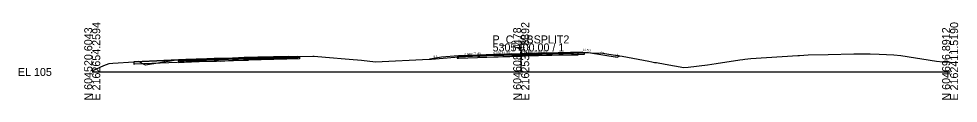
# Model space of a CAD drawing. Extents: x -26 to 1303, y -10 to 12033.
# Drawn here: x 974.3 to 1302.8, y 490.3 to 517.4 of the extents above; entities that cross this region are included whole.
import ezdxf

# ---------------------------------------------------------------- set-up
doc = ezdxf.new("R2010")
doc.units = 0
for name, color, linetype in [('RD_GPK_XS_Cell', 7, 'Continuous'), ('RD_XS_Base', 7, 'Continuous'), ('RD_XS_ExGround', 7, 'Continuous'), ('RD_XS_ExPaveRet', 7, 'Continuous'), ('RD_XS_Greenside', 7, 'Continuous'), ('RD_XS_Pave', 7, 'Continuous'), ('RD_XS_PaveOvlay_CP', 7, 'Continuous'), ('RD_XS_TieSlope', 7, 'Continuous'), ('RD_XS_TX_Elev_EX', 7, 'Continuous'), ('RD_XS_TX_Elev_PR', 7, 'Continuous'), ('RD_XS_TX_ShdSlope', 7, 'Continuous'), ('RD_XS_TX_Slope', 7, 'Continuous')]:
    doc.layers.add(name, color=color, linetype=linetype)

msp = doc.modelspace()

# ---------------------------------------------------------------- linework, layer by layer
at = {"layer": 'RD_GPK_XS_Cell'}
for p, q in [((1150, 500), (1150, 510)), ((1000, 500), (1150, 500)), ((1150, 500), (1300, 500))]:
    msp.add_line(p, q, dxfattribs=at)
at = {"layer": 'RD_XS_Base'}
for p, q in [((1150, 506.05), (1138, 505.72)), ((1150, 506.05), (1171.54, 506.66)), ((1150, 505.55), (1150, 506.21)), ((1150, 506.21), (1150, 506.21)), ((1150, 506.21), (1150, 506.21)), ((1150, 506.21), (1150, 506.05)), ((1172.04, 506.17), (1150, 505.55)), ((1150, 506.05), (1150, 506.05)), ((1150, 505.55), (1150, 506.05)), ((1150, 506.05), (1150, 506.05)), ((1150, 506.05), (1150, 506.05)), ((1162, 506.39), (1162, 506.39)), ((1162, 506.39), (1162, 506.39)), ((1171.54, 506.66), (1171.54, 506.66)), ((1172.04, 506.67), (1172.04, 506.17)), ((1172.04, 506.64), (1172.04, 506.64)), ((1030.19, 503.86), (1030.13, 503.86)), ((1030.13, 503.86), (1030.13, 503.42)), ((1030.13, 503.42), (1030.13, 503.36)), ((1030.13, 503.36), (1030.19, 503.36)), ((1030.63, 503.88), (1030.19, 503.86)), ((1030.19, 503.36), (1030.63, 503.38)), ((1032.1, 503.94), (1030.63, 503.88)), ((1030.63, 503.38), (1032.1, 503.44)), ((1042.63, 504.36), (1032.1, 503.94)), ((1032.1, 503.44), (1042.63, 503.86)), ((1044.14, 504.4), (1042.63, 504.36)), ((1042.63, 503.86), (1044.14, 503.9)), ((1054.63, 504.67), (1044.14, 504.4)), ((1044.14, 503.9), (1054.63, 504.17)), ((1054.63, 504.67), (1072.44, 505.13)), ((1054.63, 504.17), (1054.63, 504.83)), ((1054.63, 504.83), (1054.63, 504.83)), ((1054.63, 504.83), (1054.63, 504.83)), ((1054.63, 504.83), (1054.63, 504.67)), ((1054.63, 504.67), (1054.63, 504.67)), ((1054.63, 504.17), (1054.63, 504.67)), ((1054.63, 504.67), (1054.63, 504.67)), ((1054.63, 504.67), (1054.63, 504.67)), ((1072.44, 504.63), (1054.63, 504.17)), ((1054.63, 504.17), (1054.63, 504.17)), ((1071.94, 505.12), (1071.94, 505.12)), ((1072.44, 505.13), (1072.44, 504.63)), ((1072.44, 505.1), (1072.44, 505.1)), ((1128.08, 505.32), (1127.58, 505.3)), ((1127.58, 505.3), (1127.58, 505.3)), ((1127.58, 505.3), (1127.58, 504.8)), ((1127.58, 504.8), (1128.08, 504.82)), ((1138, 505.72), (1128.08, 505.32)), ((1128.08, 505.32), (1128.08, 505.32)), ((1128.08, 504.82), (1138, 505.22)), ((1128.08, 504.82), (1128.08, 504.82)), ((1138, 505.72), (1138, 505.72)), ((1138, 505.22), (1150, 505.55)), ((1138, 505.22), (1138, 505.22)), ((1150, 505.55), (1150, 505.55)), ((1162, 505.89), (1162, 505.89)), ((1162, 505.89), (1162, 505.89))]:
    msp.add_line(p, q, dxfattribs=at)
at = {"layer": 'RD_XS_ExGround'}
msp.add_lwpolyline([(1000, 500.38), (1004.09, 502.24), (1005.95, 502.99), (1007.16, 503.04), (1014.5, 503.53), (1033.44, 504.37), (1036.42, 504.49), (1042.96, 504.55), (1044.68, 504.73), (1045.03, 504.59), (1049.17, 504.86), (1053.17, 505.06), (1057.99, 505.21), (1063.44, 505.35), (1068.59, 505.43), (1077.12, 505.52), (1077.63, 505.53), (1081.56, 505.2), (1089.83, 504.5), (1094.2, 504.08), (1099.09, 503.58), (1117.86, 504.48), (1118.23, 504.5), (1118.6, 504.53), (1135, 505.89), (1140.45, 506.08), (1149.92, 506.38), (1150.27, 506.38), (1151.05, 506.43), (1152.22, 506.46), (1156.04, 506.54), (1160.68, 506.64), (1168.98, 506.76), (1169.88, 506.77), (1170.49, 506.76), (1178.54, 506.55), (1180.71, 506.2), (1185.37, 505.5), (1194.6, 503.76), (1195.68, 503.56), (1196.66, 503.37), (1197.27, 503.26), (1200.32, 502.72), (1206.91, 501.55), (1208.45, 501.72), (1215.14, 502.48), (1218.24, 502.99), (1226.49, 504.24), (1227.52, 504.41), (1228.18, 504.5), (1230.27, 504.66), (1246.74, 505.8), (1247.32, 505.81), (1250.35, 505.95), (1257.31, 506.11), (1266.34, 506.33), (1270.07, 506.36), (1272, 506.39), (1275.17, 506.18), (1280.29, 506.03), (1282.83, 505.75), (1295.24, 503.81), (1297.49, 503.56), (1299.13, 503.54), (1300, 503.44)], dxfattribs=at)
at = {"layer": 'RD_XS_ExPaveRet'}
for points in [[(1169.88, 506.77), (1168.98, 506.76), (1168.98, 506.76), (1160.68, 506.64), (1160.68, 506.64), (1160.68, 506.64), (1156.04, 506.54), (1156.04, 506.54), (1156.04, 506.54), (1152.22, 506.46), (1151.05, 506.43), (1151.05, 506.43), (1150.27, 506.38), (1150.27, 506.38), (1149.92, 506.38), (1149.92, 506.38), (1149.92, 506.38), (1140.45, 506.08), (1140.45, 506.08), (1135, 505.89), (1135, 505.89), (1135, 505.14), (1140.45, 505.33), (1140.45, 505.33), (1149.92, 505.63), (1149.92, 505.63), (1149.92, 505.63), (1150.27, 505.63), (1150.27, 505.63), (1151.05, 505.68), (1151.05, 505.68), (1152.22, 505.71), (1156.04, 505.79), (1156.04, 505.79), (1156.04, 505.79), (1160.68, 505.89), (1160.68, 505.89), (1160.68, 505.89), (1168.98, 506.01), (1168.98, 506.01), (1169.88, 506.02), (1169.88, 506.02), (1169.88, 506.77), (1169.88, 506.77), (1169.88, 506.77)], [(1169.88, 506.77), (1168.98, 506.76), (1160.68, 506.64), (1156.04, 506.54), (1152.22, 506.46), (1151.05, 506.43), (1150.27, 506.38), (1149.92, 506.38), (1140.45, 506.08), (1135, 505.89), (1135, 505.14), (1140.45, 505.33), (1149.92, 505.63), (1150.27, 505.63), (1151.05, 505.68), (1152.22, 505.71), (1156.04, 505.79), (1160.68, 505.89), (1168.98, 506.01), (1169.88, 506.02), (1169.88, 506.02), (1169.88, 506.77), (1169.88, 506.77)], [(1063.44, 505.35), (1058.03, 505.21), (1057.99, 505.21), (1057.87, 505.21), (1053.17, 505.06), (1053.11, 505.06), (1049.17, 504.86), (1049.1, 504.86), (1049.09, 504.86), (1045.02, 504.59), (1044.92, 504.59), (1044.68, 504.69), (1043.49, 504.56), (1043.38, 504.56), (1036.55, 504.49), (1036.45, 504.49), (1036.43, 504.48), (1036.39, 504.48), (1033.24, 504.36), (1032.78, 504.34), (1014.84, 503.55), (1014.5, 503.53), (1014.5, 503.53), (1014.5, 503.53), (1014.5, 503.5), (1014.5, 502.78), (1014.5, 502.78), (1014.5, 502.78), (1014.84, 502.8), (1032.78, 503.59), (1033.24, 503.61), (1036.39, 503.73), (1036.43, 503.73), (1036.45, 503.74), (1036.55, 503.74), (1043.38, 503.81), (1043.49, 503.81), (1044.68, 503.94), (1044.92, 503.84), (1045.02, 503.84), (1049.09, 504.11), (1049.1, 504.11), (1049.17, 504.11), (1053.11, 504.3), (1053.17, 504.31), (1057.87, 504.46), (1057.99, 504.46), (1058.03, 504.46), (1063.44, 504.6), (1063.56, 504.6), (1068.59, 504.68), (1068.59, 505.42), (1068.59, 505.43), (1063.56, 505.35), (1063.44, 505.35)], [(1063.44, 505.35), (1058.03, 505.21), (1057.99, 505.21), (1057.87, 505.21), (1053.17, 505.06), (1053.11, 505.06), (1049.17, 504.86), (1049.1, 504.86), (1049.09, 504.86), (1045.02, 504.59), (1044.92, 504.59), (1044.68, 504.69), (1043.49, 504.56), (1043.38, 504.56), (1036.55, 504.49), (1036.45, 504.49), (1036.43, 504.48), (1036.39, 504.48), (1033.24, 504.36), (1032.78, 504.34), (1014.84, 503.55), (1014.5, 503.53), (1014.5, 503.53), (1014.5, 503.5), (1014.5, 502.78), (1014.5, 502.78), (1014.84, 502.8), (1032.78, 503.59), (1033.24, 503.61), (1036.39, 503.73), (1036.43, 503.73), (1036.45, 503.74), (1036.55, 503.74), (1043.38, 503.81), (1043.49, 503.81), (1044.68, 503.94), (1044.92, 503.84), (1045.02, 503.84), (1049.09, 504.11), (1049.1, 504.11), (1049.17, 504.11), (1053.11, 504.3), (1053.17, 504.31), (1057.87, 504.46), (1057.99, 504.46), (1058.03, 504.46), (1063.44, 504.6), (1063.56, 504.6), (1068.59, 504.68), (1068.59, 505.42), (1068.59, 505.43), (1063.56, 505.35), (1063.44, 505.35)]]:
    msp.add_lwpolyline(points, dxfattribs=at)
at = {"layer": 'RD_XS_Greenside'}
for p, q in [((1173.54, 506.81), (1183.54, 505.15)), ((1018.63, 502.37), (1016.16, 503.61)), ((1028.63, 504.04), (1018.63, 502.37)), ((1122.08, 505.16), (1118.07, 504.49)), ((1183.54, 505.15), (1184.5, 505.63))]:
    msp.add_line(p, q, dxfattribs=at)
at = {"layer": 'RD_XS_Pave'}
for p, q in [((1138, 506.04), (1128.08, 505.64)), ((1150, 506.37), (1138, 506.04)), ((1138, 505.88), (1150, 506.21)), ((1150, 506.21), (1138, 505.88)), ((1138, 505.72), (1150, 506.05)), ((1138, 506.04), (1138, 506.04)), ((1171.54, 506.97), (1150, 506.37)), ((1171.54, 506.82), (1150, 506.21)), ((1150, 506.21), (1171.54, 506.82)), ((1150, 506.05), (1172.04, 506.67)), ((1150, 506.37), (1150, 506.37)), ((1150, 506.21), (1150, 506.21)), ((1150, 506.21), (1150, 506.21)), ((1150, 506.21), (1150, 506.05)), ((1150, 506.21), (1150, 506.21)), ((1150, 506.05), (1150, 506.21)), ((1150, 506.21), (1150, 506.21)), ((1150, 506.21), (1150, 506.21)), ((1150, 506.05), (1150, 506.05)), ((1150, 506.05), (1150, 506.05)), ((1162, 506.71), (1162, 506.71)), ((1162, 506.71), (1162, 506.71)), ((1162, 506.55), (1162, 506.55)), ((1162, 506.55), (1162, 506.55)), ((1162, 506.55), (1162, 506.55)), ((1162, 506.55), (1162, 506.55)), ((1162, 506.39), (1162, 506.39)), ((1162, 506.39), (1162, 506.39)), ((1171.54, 506.82), (1171.54, 506.97)), ((1171.54, 506.97), (1171.54, 506.97)), ((1171.54, 506.66), (1171.54, 506.82)), ((1171.54, 506.82), (1171.54, 506.82)), ((1032.1, 504.26), (1030.63, 504.2)), ((1030.63, 504.2), (1030.63, 504.06)), ((1030.63, 504.04), (1032.1, 504.1)), ((1032.1, 504.1), (1030.63, 504.04)), ((1030.63, 504.06), (1030.63, 504.04)), ((1030.63, 504.04), (1030.63, 503.9)), ((1030.63, 503.88), (1032.1, 503.94)), ((1030.63, 503.9), (1030.63, 503.88)), ((1042.63, 504.68), (1032.1, 504.26)), ((1032.1, 504.1), (1042.63, 504.52)), ((1042.63, 504.52), (1032.1, 504.1)), ((1032.1, 503.94), (1042.63, 504.36)), ((1044.14, 504.72), (1042.63, 504.68)), ((1042.63, 504.52), (1044.14, 504.56)), ((1044.14, 504.56), (1042.63, 504.52)), ((1042.63, 504.36), (1044.14, 504.4)), ((1054.63, 504.99), (1044.14, 504.72)), ((1044.14, 504.56), (1054.63, 504.83)), ((1054.63, 504.83), (1044.14, 504.56)), ((1044.14, 504.4), (1054.63, 504.67)), ((1071.94, 505.44), (1054.63, 504.99)), ((1071.94, 505.28), (1054.63, 504.83)), ((1054.63, 504.83), (1071.94, 505.28)), ((1054.63, 504.67), (1071.94, 505.12)), ((1054.63, 504.99), (1054.63, 504.99)), ((1054.63, 504.83), (1054.63, 504.83)), ((1054.63, 504.83), (1054.63, 504.83)), ((1054.63, 504.83), (1054.63, 504.67)), ((1054.63, 504.83), (1054.63, 504.83)), ((1054.63, 504.67), (1054.63, 504.83)), ((1054.63, 504.83), (1054.63, 504.83)), ((1054.63, 504.83), (1054.63, 504.83)), ((1054.63, 504.67), (1054.63, 504.67)), ((1054.63, 504.67), (1054.63, 504.67)), ((1071.94, 505.28), (1071.94, 505.44)), ((1071.94, 505.44), (1071.94, 505.44)), ((1071.94, 505.12), (1071.94, 505.28)), ((1071.94, 505.28), (1071.94, 505.28)), ((1128.08, 505.48), (1138, 505.88)), ((1138, 505.88), (1128.08, 505.48)), ((1128.08, 505.32), (1138, 505.72)), ((1128.08, 505.64), (1128.08, 505.64)), ((1128.08, 505.64), (1128.08, 505.48)), ((1128.08, 505.48), (1128.08, 505.48)), ((1128.08, 505.48), (1128.08, 505.32)), ((1138, 505.88), (1138, 505.88)), ((1138, 505.88), (1138, 505.88)), ((1138, 505.72), (1138, 505.72))]:
    msp.add_line(p, q, dxfattribs=at)
at = {"layer": 'RD_XS_PaveOvlay_CP'}
for p, q in [((1138, 506.04), (1128.08, 505.64)), ((1150, 506.37), (1138, 506.04)), ((1138, 506.04), (1138, 506.04)), ((1171.54, 506.97), (1150, 506.37)), ((1150, 506.37), (1150, 506.37)), ((1162, 506.71), (1162, 506.71)), ((1162, 506.71), (1162, 506.71)), ((1032.1, 504.26), (1030.63, 504.2)), ((1042.63, 504.68), (1032.1, 504.26)), ((1044.14, 504.72), (1042.63, 504.68)), ((1054.63, 504.99), (1044.14, 504.72)), ((1071.94, 505.44), (1054.63, 504.99)), ((1054.63, 504.99), (1054.63, 504.99))]:
    msp.add_line(p, q, dxfattribs=at)
at = {"layer": 'RD_XS_TieSlope'}
for p, q in [((1171.54, 506.97), (1173.54, 506.81)), ((1030.63, 504.2), (1028.63, 504.04)), ((1071.94, 505.44), (1077.37, 505.53)), ((1128.08, 505.64), (1122.08, 505.16))]:
    msp.add_line(p, q, dxfattribs=at)

# ---------------------------------------------------------------- texts
at = {"layer": 'RD_GPK_XS_Cell'}
for s, p in [('E 2162654.2594', (1002.8, 490)), ('E 2162532.8892', (1152.8, 490)), ('E 2162411.5190', (1302.8, 490)), ('N 604520.6043', (1000, 490)), ('N 604608.7478', (1150, 490)), ('N 604696.8912', (1300, 490))]:
    msp.add_text(s, height=2.8, rotation=90, dxfattribs=at).set_placement(p)
for s, p in [('P_C_SBSPLIT2', (1140, 510)), ('5305+00.00 / 1', (1140, 507.2)), ('EL 105', (974, 498.6))]:
    msp.add_text(s, height=2.8, dxfattribs=at).set_placement(p)
at = {"layer": 'RD_XS_TX_Elev_EX'}
msp.add_text('111.38', height=0.6, rotation=90, dxfattribs=at).set_placement((1149.7, 507.26))
at = {"layer": 'RD_XS_TX_Elev_PR'}
msp.add_text('111.37', height=1, rotation=90, dxfattribs=at).set_placement((1151.28, 506.67))
at = {"layer": 'RD_XS_TX_ShdSlope'}
msp.add_text('12.5:1', height=0.75, rotation=355.4261, dxfattribs=at).set_placement((1171.47, 507.42))
at = {"layer": 'RD_XS_TX_Slope'}
for s, rotation, p in [('0.040 FT./FT.', 2.2906, (1130.15, 505.82)), ('0.030 FT./FT.', 1.7184, (1140.36, 506.29)), ('0.030 FT./FT.', 1.7184, (1153.16, 506.62)), ('6:1', 350.5358, (1177.67, 506.48)), ('2:1', 26.5651, (1182.93, 505.23)), ('6:1', 9.4623, (1119.36, 505.01))]:
    msp.add_text(s, height=0.75, rotation=rotation, dxfattribs=at).set_placement(p)

doc.saveas('drawing.dxf')
